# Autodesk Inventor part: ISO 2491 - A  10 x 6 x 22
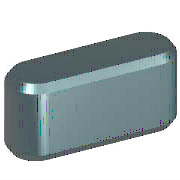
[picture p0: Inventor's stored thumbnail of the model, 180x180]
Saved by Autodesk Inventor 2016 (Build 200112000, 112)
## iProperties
IsCustomPart: 0
Created: 2013-10
Part Number: ISO 2491 - A  10 x 6 x 22
Material: Stainless Steel, 440C
Description: SHAFT KEY SST
Document SubType Name: Modeling
Standard: ISO 2491
Designer: normanpa
Standard Revision: First edition 1974-08-15
Standards Organization: ISO
Language: en-US
Size Designation: A  10 x 6 x 22
Categories: <MemberInstance><Categories><Category DisplayName="Shaft Parts" InternalName="7f7aeb1f-a693-4053-b835-cee3144e0d98" Mnemonic="SHFT"><Category DisplayName="Keys"
Density: 7.75 g/cm^3
Appearance: Semi-Polished
Mass: 9.081 g
Surface Area: 6.89684 cm^2
Volume: 1.17174 cm^3
Author: Autodesk
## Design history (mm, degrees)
sketch "Sketch1"
  geometry: L1 (5, 5)-(17, 5); L2 (17, -5)-(5, -5); L3 (0, 9.4)-(0, -7.4) reference; L4 (-5, 0)-(30, 0) reference; L5 (22, 0)-(22, 7); A1 r 5 centre (5, 0) between (5, 5) and (5, -5); A2 r 5 centre (17, 0) between (17, -5) and (17, 5)
  constraints: 6 end point, 5 point on circle, 4 tangent, 3 point on line, 2 centre point, 1 horizontal, 1 parallel, 1 perpendicular
  dimensions: "d0" = 5 radius of A1 (= 0.5 x PB); "d13" = 5 radius of A2 (= 0.5 x PB); "d14" = 22 distance between parallel lines of L5 L3 (= NLG)
extrude "Body1" new body sketch "Sketch1" taper "d3" = 0 deg; stored distance "d4" = 10
workplane "Work Plane3"
body "Solid1"
workplane "Work Plane1"
workplane "Work Plane2"
chamfer "Chamfer1" distance "d8" = 0.6 (= PHH); stored, may be unused: second distance "d9" = 0.6 (= PHH), angle "d15" = 45 deg
other parameters: "d1" = -3.5 (= -PNT), "d2" = 2.5 (= PH - PNT), "NLG" = 22 [user parameter; used in 1 equation term], "PNT" = 3.5 [user parameter; used in 2 equation terms], "PH" = 6 [user parameter; used in 1 equation term], "PHH" = 0.6 [user parameter; used in 2 equation terms], "d10" = 0, "d16" = 0, "d17" = 0, "d18" = 0, "RR" = 0.25 [user parameter], "WDMAX" = 38 [user parameter], "PLB1" = 22 [user parameter], "PLB2" = 22 [user parameter], "PUEB" = 2.8 [user parameter]
